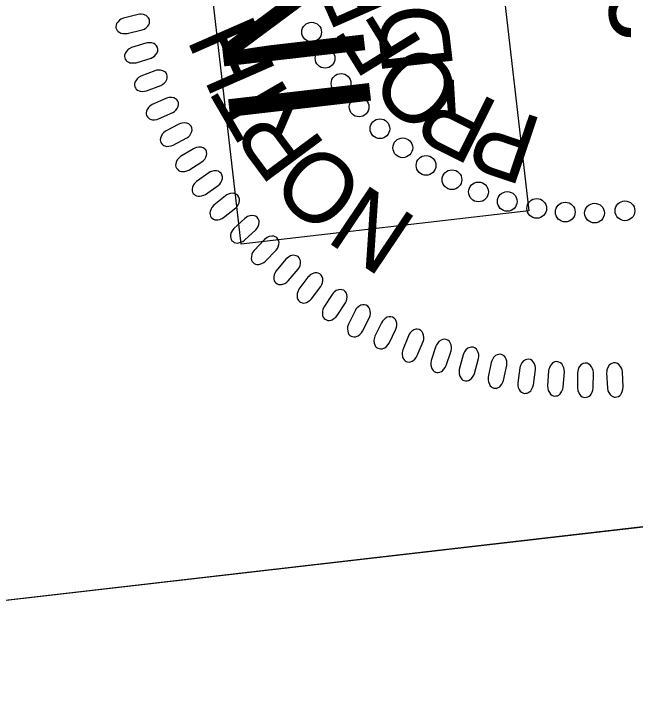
# Model space of a CAD drawing. Extents: x 477607 to 479438, y 495543 to 499482.
# Drawn here: x 477704.9 to 477755.3, y 497193.8 to 497250.4 of the extents above; entities that cross this region are included whole.
import ezdxf

# ---------------------------------------------------------------- set-up
doc = ezdxf.new("R2010")
doc.units = 0
for name, color, linetype in [('Sheet Border Standard 30in CELL', 7, 'Continuous'), ('Sheet Layout Plan Border', 7, 'Continuous'), ('Sheet PE Seal Cell', 7, 'Continuous'), ('Sheet Plan CELL', 7, 'Continuous'), ('Sheet Sticker Incomplete CELL', 7, 'Continuous')]:
    doc.layers.add(name, color=color, linetype=linetype)

msp = doc.modelspace()

# ---------------------------------------------------------------- linework, layer by layer
at = {"layer": 'Sheet Border Standard 30in CELL'}
msp.add_lwpolyline([(477693.829, 497201.611), (477682.369, 497301.002), (477794.128, 497313.888), (477805.588, 497214.497)], close=True, dxfattribs=at)
at = {"layer": 'Sheet Layout Plan Border'}
msp.add_lwpolyline([(478060.611, 495968.966), (478655.257, 496063.069), (478848.534, 496026.024), (478735.995, 497002.058), (478709.928, 496998.314), (478420.128, 496964.9), (478384.13, 497277.103), (478673.93, 497310.517), (478699.758, 497316.337), (478696.236, 497346.887), (478616.747, 497337.721), (478607.505, 497417.875), (478188.47, 497393.351), (477955.381, 497379.709), (477811.168, 497371.269), (477828.931, 497217.213), (477697.933, 497202.084), (477716.324, 497043.314), (477674.836, 497038.508), (477805.454, 495905.894)], close=True, dxfattribs=at)
msp.add_lwpolyline([(478060.611, 495968.966), (478655.257, 496063.069), (478848.534, 496026.024), (478735.995, 497002.058), (478709.928, 496998.314), (478420.128, 496964.9), (478384.13, 497277.103), (478673.93, 497310.517), (478699.758, 497316.337), (478696.236, 497346.887), (478616.747, 497337.721), (478607.505, 497417.875), (478188.47, 497393.351), (477955.381, 497379.709), (477811.168, 497371.269), (477828.931, 497217.213), (477697.933, 497202.084), (477716.324, 497043.314), (477674.836, 497038.508), (477805.454, 495905.894)], close=True, dxfattribs=at)
at = {"layer": 'Sheet PE Seal Cell'}
for points in [[(477714.949, 497250.395), (477713.758, 497250.103), (477713.553, 497250.015), (477713.43, 497249.931), (477713.292, 497249.781), (477713.209, 497249.661), (477713.158, 497249.533), (477713.144, 497249.422), (477713.151, 497249.308), (477713.198, 497249.204), (477713.255, 497249.095), (477713.338, 497249.007), (477713.46, 497248.929), (477713.552, 497248.891), (477713.713, 497248.86), (477713.901, 497248.845), (477714.062, 497248.861), (477715.284, 497249.153), (477715.443, 497249.215), (477715.568, 497249.292), (477715.702, 497249.417), (477715.811, 497249.559), (477715.865, 497249.672), (477715.886, 497249.839), (477715.87, 497249.989), (477715.796, 497250.125), (477715.722, 497250.215), (477715.595, 497250.314), (477715.402, 497250.39), (477715.212, 497250.413), (477715.079, 497250.411)], [(477715.587, 497248.071), (477714.417, 497247.706), (477714.219, 497247.604), (477714.101, 497247.513), (477713.973, 497247.355), (477713.897, 497247.23), (477713.854, 497247.099), (477713.847, 497246.987), (477713.861, 497246.874), (477713.914, 497246.773), (477713.978, 497246.668), (477714.067, 497246.586), (477714.193, 497246.515), (477714.287, 497246.482), (477714.45, 497246.463), (477714.639, 497246.459), (477714.798, 497246.485), (477716, 497246.853), (477716.155, 497246.925), (477716.275, 497247.009), (477716.4, 497247.143), (477716.5, 497247.292), (477716.547, 497247.408), (477716.558, 497247.576), (477716.532, 497247.724), (477716.449, 497247.855), (477716.37, 497247.94), (477716.237, 497248.032), (477716.04, 497248.096), (477715.849, 497248.106), (477715.716, 497248.096)], [(477716.321, 497245.835), (477715.175, 497245.397), (477714.984, 497245.283), (477714.872, 497245.184), (477714.754, 497245.019), (477714.686, 497244.889), (477714.652, 497244.756), (477714.651, 497244.643), (477714.673, 497244.532), (477714.732, 497244.434), (477714.803, 497244.333), (477714.896, 497244.257), (477715.027, 497244.195), (477715.122, 497244.168), (477715.287, 497244.158), (477715.475, 497244.167), (477715.632, 497244.202), (477716.808, 497244.645), (477716.959, 497244.727), (477717.073, 497244.819), (477717.19, 497244.96), (477717.28, 497245.114), (477717.32, 497245.233), (477717.32, 497245.402), (477717.285, 497245.548), (477717.194, 497245.674), (477717.11, 497245.754), (477716.972, 497245.836), (477716.771, 497245.887), (477716.579, 497245.886), (477716.448, 497245.868)], [(477717.205, 497243.588), (477716.089, 497243.078), (477715.905, 497242.954), (477715.8, 497242.848), (477715.692, 497242.676), (477715.632, 497242.541), (477715.607, 497242.406), (477715.614, 497242.294), (477715.642, 497242.184), (477715.707, 497242.09), (477715.784, 497241.994), (477715.881, 497241.924), (477716.016, 497241.87), (477716.113, 497241.849), (477716.278, 497241.85), (477716.466, 497241.87), (477716.62, 497241.916), (477717.766, 497242.431), (477717.911, 497242.522), (477718.019, 497242.621), (477718.127, 497242.769), (477718.207, 497242.929), (477718.24, 497243.05), (477718.229, 497243.218), (477718.185, 497243.362), (477718.086, 497243.482), (477717.997, 497243.556), (477717.854, 497243.63), (477717.65, 497243.669), (477717.459, 497243.655), (477717.328, 497243.629)], [(477718.268, 497241.495), (477717.186, 497240.916), (477717.01, 497240.78), (477716.912, 497240.668), (477716.815, 497240.489), (477716.764, 497240.352), (477716.747, 497240.215), (477716.761, 497240.104), (477716.797, 497239.996), (477716.868, 497239.906), (477716.95, 497239.815), (477717.052, 497239.751), (477717.19, 497239.706), (477717.288, 497239.691), (477717.452, 497239.702), (477717.638, 497239.734), (477717.789, 497239.789), (477718.901, 497240.376), (477719.039, 497240.476), (477719.141, 497240.581), (477719.24, 497240.736), (477719.31, 497240.9), (477719.335, 497241.023), (477719.313, 497241.19), (477719.26, 497241.332), (477719.154, 497241.444), (477719.061, 497241.513), (477718.913, 497241.578), (477718.707, 497241.604), (477718.517, 497241.578), (477718.389, 497241.543)], [(477719.437, 497239.499), (477718.394, 497238.853), (477718.227, 497238.706), (477718.136, 497238.588), (477718.05, 497238.404), (477718.009, 497238.263), (477718, 497238.126), (477718.021, 497238.015), (477718.063, 497237.91), (477718.139, 497237.825), (477718.227, 497237.739), (477718.333, 497237.682), (477718.473, 497237.645), (477718.572, 497237.636), (477718.735, 497237.657), (477718.919, 497237.701), (477719.067, 497237.766), (477720.138, 497238.421), (477720.272, 497238.53), (477720.366, 497238.641), (477720.454, 497238.802), (477720.515, 497238.971), (477720.531, 497239.095), (477720.499, 497239.26), (477720.438, 497239.398), (477720.325, 497239.504), (477720.228, 497239.566), (477720.076, 497239.622), (477719.869, 497239.635), (477719.681, 497239.597), (477719.555, 497239.554)], [(477720.683, 497237.546), (477719.682, 497236.835), (477719.525, 497236.678), (477719.441, 497236.555), (477719.368, 497236.365), (477719.335, 497236.223), (477719.334, 497236.085), (477719.363, 497235.977), (477719.411, 497235.873), (477719.492, 497235.794), (477719.586, 497235.713), (477719.695, 497235.663), (477719.837, 497235.635), (477719.937, 497235.632), (477720.098, 497235.664), (477720.279, 497235.719), (477720.422, 497235.793), (477721.451, 497236.514), (477721.576, 497236.63), (477721.664, 497236.748), (477721.742, 497236.913), (477721.792, 497237.086), (477721.8, 497237.211), (477721.758, 497237.374), (477721.688, 497237.507), (477721.569, 497237.606), (477721.468, 497237.663), (477721.313, 497237.709), (477721.105, 497237.708), (477720.92, 497237.659), (477720.797, 497237.608)], [(477722.049, 497235.672), (477721.095, 497234.901), (477720.947, 497234.734), (477720.872, 497234.606), (477720.81, 497234.412), (477720.786, 497234.267), (477720.794, 497234.13), (477720.829, 497234.023), (477720.884, 497233.924), (477720.97, 497233.849), (477721.069, 497233.775), (477721.181, 497233.731), (477721.324, 497233.712), (477721.424, 497233.716), (477721.583, 497233.758), (477721.76, 497233.824), (477721.898, 497233.907), (477722.88, 497234.692), (477722.998, 497234.815), (477723.078, 497234.938), (477723.146, 497235.108), (477723.184, 497235.283), (477723.185, 497235.409), (477723.132, 497235.569), (477723.054, 497235.697), (477722.929, 497235.789), (477722.824, 497235.838), (477722.667, 497235.875), (477722.46, 497235.861), (477722.278, 497235.8), (477722.159, 497235.742)], [(477723.623, 497233.84), (477722.72, 497233.01), (477722.583, 497232.834), (477722.515, 497232.702), (477722.466, 497232.504), (477722.452, 497232.358), (477722.469, 497232.222), (477722.51, 497232.117), (477722.571, 497232.022), (477722.662, 497231.952), (477722.764, 497231.885), (477722.879, 497231.848), (477723.024, 497231.838), (477723.123, 497231.848), (477723.279, 497231.9), (477723.452, 497231.977), (477723.584, 497232.069), (477724.515, 497232.913), (477724.624, 497233.045), (477724.697, 497233.172), (477724.754, 497233.345), (477724.781, 497233.523), (477724.774, 497233.648), (477724.712, 497233.804), (477724.625, 497233.928), (477724.495, 497234.011), (477724.388, 497234.054), (477724.228, 497234.081), (477724.022, 497234.054), (477723.844, 497233.982), (477723.729, 497233.916)], [(477725.218, 497232.131), (477724.369, 497231.246), (477724.244, 497231.062), (477724.185, 497230.925), (477724.148, 497230.725), (477724.142, 497230.579), (477724.168, 497230.444), (477724.216, 497230.343), (477724.283, 497230.25), (477724.378, 497230.187), (477724.485, 497230.126), (477724.601, 497230.096), (477724.746, 497230.096), (477724.845, 497230.112), (477724.997, 497230.173), (477725.164, 497230.261), (477725.291, 497230.361), (477726.167, 497231.262), (477726.268, 497231.4), (477726.332, 497231.532), (477726.378, 497231.708), (477726.394, 497231.887), (477726.379, 497232.012), (477726.307, 497232.164), (477726.213, 497232.282), (477726.078, 497232.356), (477725.968, 497232.393), (477725.807, 497232.409), (477725.604, 497232.369), (477725.431, 497232.286), (477725.319, 497232.214)], [(477726.952, 497230.531), (477726.16, 497229.595), (477726.046, 497229.403), (477725.996, 497229.263), (477725.972, 497229.061), (477725.975, 497228.915), (477726.009, 497228.781), (477726.063, 497228.683), (477726.136, 497228.595), (477726.235, 497228.538), (477726.346, 497228.484), (477726.464, 497228.462), (477726.608, 497228.47), (477726.706, 497228.492), (477726.853, 497228.563), (477727.015, 497228.662), (477727.135, 497228.768), (477727.953, 497229.724), (477728.045, 497229.867), (477728.101, 497230.003), (477728.135, 497230.182), (477728.14, 497230.362), (477728.118, 497230.486), (477728.037, 497230.633), (477727.935, 497230.744), (477727.795, 497230.81), (477727.683, 497230.84), (477727.522, 497230.846), (477727.321, 497230.794), (477727.154, 497230.7), (477727.047, 497230.621)], [(477728.741, 497229.064), (477728.009, 497228.08), (477727.908, 497227.881), (477727.867, 497227.738), (477727.855, 497227.535), (477727.868, 497227.389), (477727.91, 497227.258), (477727.971, 497227.164), (477728.049, 497227.081), (477728.15, 497227.03), (477728.264, 497226.983), (477728.384, 497226.968), (477728.527, 497226.986), (477728.623, 497227.014), (477728.767, 497227.094), (477728.921, 497227.202), (477729.035, 497227.317), (477729.791, 497228.321), (477729.874, 497228.47), (477729.921, 497228.609), (477729.944, 497228.791), (477729.938, 497228.969), (477729.908, 497229.092), (477729.817, 497229.233), (477729.709, 497229.338), (477729.565, 497229.395), (477729.452, 497229.418), (477729.29, 497229.414), (477729.093, 497229.349), (477728.932, 497229.245), (477728.831, 497229.159)], [(477730.701, 497227.666), (477730.032, 497226.638), (477729.944, 497226.433), (477729.912, 497226.288), (477729.913, 497226.085), (477729.935, 497225.94), (477729.985, 497225.812), (477730.051, 497225.722), (477730.135, 497225.644), (477730.239, 497225.599), (477730.356, 497225.56), (477730.476, 497225.552), (477730.618, 497225.579), (477730.712, 497225.613), (477730.85, 497225.702), (477730.998, 497225.82), (477731.104, 497225.941), (477731.795, 497226.99), (477731.869, 497227.145), (477731.907, 497227.286), (477731.919, 497227.469), (477731.901, 497227.647), (477731.863, 497227.767), (477731.764, 497227.903), (477731.65, 497228), (477731.503, 497228.049), (477731.388, 497228.064), (477731.227, 497228.05), (477731.035, 497227.973), (477730.88, 497227.859), (477730.784, 497227.766)], [(477732.567, 497226.346), (477732.023, 497225.247), (477731.96, 497225.033), (477731.945, 497224.885), (477731.97, 497224.683), (477732.009, 497224.542), (477732.074, 497224.421), (477732.15, 497224.339), (477732.242, 497224.272), (477732.351, 497224.239), (477732.472, 497224.214), (477732.592, 497224.22), (477732.73, 497224.264), (477732.819, 497224.309), (477732.945, 497224.413), (477733.079, 497224.548), (477733.17, 497224.681), (477733.733, 497225.804), (477733.788, 497225.966), (477733.809, 497226.111), (477733.8, 497226.294), (477733.761, 497226.468), (477733.709, 497226.583), (477733.595, 497226.706), (477733.47, 497226.79), (477733.318, 497226.821), (477733.202, 497226.822), (477733.044, 497226.79), (477732.862, 497226.691), (477732.722, 497226.559), (477732.638, 497226.456)], [(477734.715, 497225.372), (477734.181, 497224.268), (477734.119, 497224.054), (477734.105, 497223.906), (477734.131, 497223.704), (477734.171, 497223.563), (477734.237, 497223.442), (477734.314, 497223.361), (477734.407, 497223.294), (477734.517, 497223.263), (477734.637, 497223.238), (477734.757, 497223.246), (477734.895, 497223.29), (477734.984, 497223.336), (477735.11, 497223.442), (477735.241, 497223.577), (477735.331, 497223.711), (477735.885, 497224.839), (477735.939, 497225.001), (477735.96, 497225.146), (477735.948, 497225.329), (477735.909, 497225.503), (477735.856, 497225.618), (477735.74, 497225.74), (477735.614, 497225.823), (477735.463, 497225.852), (477735.347, 497225.853), (477735.189, 497225.819), (477735.008, 497225.718), (477734.869, 497225.586), (477734.785, 497225.482)], [(477736.901, 497224.312), (477736.436, 497223.176), (477736.388, 497222.959), (477736.383, 497222.81), (477736.423, 497222.61), (477736.471, 497222.472), (477736.544, 497222.356), (477736.626, 497222.28), (477736.722, 497222.218), (477736.834, 497222.195), (477736.956, 497222.177), (477737.075, 497222.193), (477737.21, 497222.246), (477737.295, 497222.297), (477737.415, 497222.41), (477737.538, 497222.553), (477737.619, 497222.693), (477738.101, 497223.853), (477738.145, 497224.018), (477738.156, 497224.164), (477738.134, 497224.346), (477738.083, 497224.518), (477738.023, 497224.628), (477737.9, 497224.743), (477737.769, 497224.818), (477737.616, 497224.837), (477737.501, 497224.832), (477737.345, 497224.787), (477737.17, 497224.675), (477737.04, 497224.535), (477736.963, 497224.426)], [(477739.137, 497223.454), (477738.745, 497222.291), (477738.71, 497222.071), (477738.715, 497221.922), (477738.767, 497221.726), (477738.824, 497221.59), (477738.905, 497221.479), (477738.992, 497221.408), (477739.091, 497221.353), (477739.204, 497221.336), (477739.327, 497221.327), (477739.445, 497221.35), (477739.576, 497221.411), (477739.658, 497221.467), (477739.77, 497221.588), (477739.884, 497221.739), (477739.957, 497221.882), (477740.365, 497223.072), (477740.398, 497223.239), (477740.4, 497223.385), (477740.366, 497223.565), (477740.304, 497223.733), (477740.238, 497223.84), (477740.108, 497223.947), (477739.973, 497224.014), (477739.819, 497224.023), (477739.703, 497224.01), (477739.551, 497223.956), (477739.383, 497223.834), (477739.263, 497223.685), (477739.193, 497223.571)], [(477741.349, 497222.763), (477741.031, 497221.579), (477741.011, 497221.357), (477741.024, 497221.208), (477741.089, 497221.015), (477741.154, 497220.884), (477741.242, 497220.779), (477741.333, 497220.713), (477741.436, 497220.664), (477741.549, 497220.655), (477741.673, 497220.653), (477741.789, 497220.683), (477741.916, 497220.752), (477741.995, 497220.813), (477742.099, 497220.941), (477742.202, 497221.099), (477742.266, 497221.247), (477742.599, 497222.458), (477742.621, 497222.628), (477742.614, 497222.774), (477742.569, 497222.951), (477742.497, 497223.116), (477742.424, 497223.218), (477742.288, 497223.317), (477742.149, 497223.374), (477741.994, 497223.375), (477741.88, 497223.353), (477741.731, 497223.291), (477741.572, 497223.158), (477741.461, 497223.001), (477741.398, 497222.884)], [(477743.625, 497222.144), (477743.382, 497220.941), (477743.375, 497220.719), (477743.398, 497220.571), (477743.474, 497220.383), (477743.548, 497220.256), (477743.642, 497220.156), (477743.736, 497220.096), (477743.843, 497220.055), (477743.956, 497220.052), (477744.08, 497220.057), (477744.194, 497220.095), (477744.316, 497220.172), (477744.391, 497220.239), (477744.487, 497220.372), (477744.581, 497220.536), (477744.634, 497220.688), (477744.891, 497221.918), (477744.903, 497222.089), (477744.886, 497222.235), (477744.83, 497222.409), (477744.748, 497222.567), (477744.669, 497222.666), (477744.527, 497222.755), (477744.384, 497222.804), (477744.229, 497222.795), (477744.117, 497222.766), (477743.972, 497222.694), (477743.822, 497222.552), (477743.72, 497222.389), (477743.665, 497222.268)], [(477745.946, 497221.703), (477745.779, 497220.487), (477745.786, 497220.265), (477745.818, 497220.119), (477745.907, 497219.936), (477745.988, 497219.814), (477746.088, 497219.719), (477746.186, 497219.666), (477746.295, 497219.631), (477746.408, 497219.635), (477746.531, 497219.648), (477746.643, 497219.693), (477746.76, 497219.778), (477746.83, 497219.849), (477746.918, 497219.988), (477747.001, 497220.158), (477747.045, 497220.312), (477747.224, 497221.556), (477747.225, 497221.727), (477747.2, 497221.872), (477747.132, 497222.042), (477747.041, 497222.195), (477746.955, 497222.288), (477746.807, 497222.369), (477746.662, 497222.409), (477746.509, 497222.39), (477746.398, 497222.355), (477746.259, 497222.273), (477746.117, 497222.122), (477746.026, 497221.953), (477745.979, 497221.828)], [(477748.285, 497221.458), (477748.195, 497220.234), (477748.216, 497220.013), (477748.257, 497219.869), (477748.357, 497219.692), (477748.445, 497219.575), (477748.552, 497219.487), (477748.653, 497219.44), (477748.763, 497219.411), (477748.876, 497219.424), (477748.998, 497219.444), (477749.106, 497219.496), (477749.218, 497219.588), (477749.284, 497219.663), (477749.362, 497219.807), (477749.435, 497219.982), (477749.469, 497220.139), (477749.57, 497221.393), (477749.56, 497221.563), (477749.525, 497221.706), (477749.448, 497221.871), (477749.346, 497222.019), (477749.255, 497222.105), (477749.103, 497222.177), (477748.955, 497222.208), (477748.803, 497222.179), (477748.695, 497222.137), (477748.561, 497222.047), (477748.429, 497221.887), (477748.349, 497221.712), (477748.31, 497221.585)], [(477750.633, 497221.305), (477750.619, 497220.078), (477750.654, 497219.859), (477750.704, 497219.718), (477750.815, 497219.547), (477750.91, 497219.436), (477751.022, 497219.355), (477751.126, 497219.315), (477751.238, 497219.293), (477751.35, 497219.312), (477751.47, 497219.341), (477751.575, 497219.399), (477751.681, 497219.498), (477751.742, 497219.577), (477751.811, 497219.726), (477751.873, 497219.904), (477751.897, 497220.064), (477751.919, 497221.32), (477751.898, 497221.49), (477751.854, 497221.63), (477751.767, 497221.79), (477751.656, 497221.932), (477751.559, 497222.012), (477751.404, 497222.074), (477751.254, 497222.096), (477751.104, 497222.057), (477750.999, 497222.009), (477750.871, 497221.911), (477750.75, 497221.742), (477750.68, 497221.563), (477750.649, 497221.434)], [(477752.994, 497221.289), (477753.057, 497220.064), (477753.106, 497219.846), (477753.165, 497219.709), (477753.286, 497219.546), (477753.389, 497219.441), (477753.505, 497219.368), (477753.611, 497219.333), (477753.725, 497219.319), (477753.835, 497219.345), (477753.954, 497219.381), (477754.055, 497219.446), (477754.154, 497219.551), (477754.21, 497219.634), (477754.269, 497219.787), (477754.32, 497219.969), (477754.334, 497220.129), (477754.277, 497221.385), (477754.245, 497221.553), (477754.193, 497221.69), (477754.095, 497221.845), (477753.976, 497221.978), (477753.875, 497222.053), (477753.715, 497222.105), (477753.565, 497222.117), (477753.418, 497222.069), (477753.315, 497222.014), (477753.194, 497221.908), (477753.083, 497221.733), (477753.025, 497221.55), (477753.002, 497221.419)]]:
    msp.add_lwpolyline(points, close=True, dxfattribs=at)
for centre in [(477729.044, 497248.964), (477730.13, 497246.845), (477731.433, 497244.806), (477732.896, 497242.89), (477734.584, 497241.12), (477736.446, 497239.571), (477738.334, 497238.145), (477740.433, 497236.984), (477742.592, 497235.99), (477744.926, 497235.216), (477747.317, 497234.65), (477749.637, 497234.355), (477752.013, 497234.268), (477754.482, 497234.455)]:
    msp.add_circle(centre, 0.801, dxfattribs=at)
at = {"layer": 'Sheet Plan CELL'}
for points in [[(478848.516, 496026.186), (477805.454, 495905.894), (477656.512, 497197.321), (477805.585, 497214.522), (477782.685, 497413.244), (478676.699, 497516.326)], [(477693.84, 497201.625), (477682.38, 497301.016), (477794.152, 497313.904), (477805.585, 497214.522)]]:
    msp.add_lwpolyline(points, close=True, dxfattribs=at)
at = {"layer": 'Sheet Sticker Incomplete CELL'}
msp.add_lwpolyline([(477746.678, 497234.443), (477723.333, 497231.751), (477706.495, 497377.784), (477729.84, 497380.475)], close=True, dxfattribs=at)

# ---------------------------------------------------------------- texts
at = {"layer": 'Sheet PE Seal Cell'}
for s, height, rotation, p in [('29470', 6.2363, 96.5586, (477759.704, 497248.641)), ('E', 5.669, 113.7459, (477736.26, 497251.06)), ('H', 5.669, 113.633, (477726.241, 497245.68)), ('F', 5.669, 121.6857, (477738.176, 497247.868)), ('O', 5.669, 137.5653, (477741.718, 497244.555)), ('R', 5.669, 153.4449, (477744.444, 497243.144)), ('T', 5.669, 120.1224, (477728.006, 497242.684)), ('R', 5.669, 126.6117, (477730.281, 497239.704)), ('P', 5.669, 161.3847, (477747.977, 497241.854)), ('O', 5.669, 139.5905, (477733.687, 497236.598)), ('N', 5.669, 146.0798, (477737.801, 497233.704))]:
    msp.add_text(s, height=height, rotation=rotation, dxfattribs=at).set_placement(p)
at = {"layer": 'Sheet Sticker Incomplete CELL'}
for s, height, p in [('INCOMPLETE PLANS', 11.52, (477734.03, 497241.994)), ('DO NOT USE FOR R/W ACQUISITION', 5.76, (477740.562, 497246.018))]:
    msp.add_text(s, height=height, rotation=96.5773, dxfattribs=at).set_placement(p)

doc.saveas('drawing.dxf')
